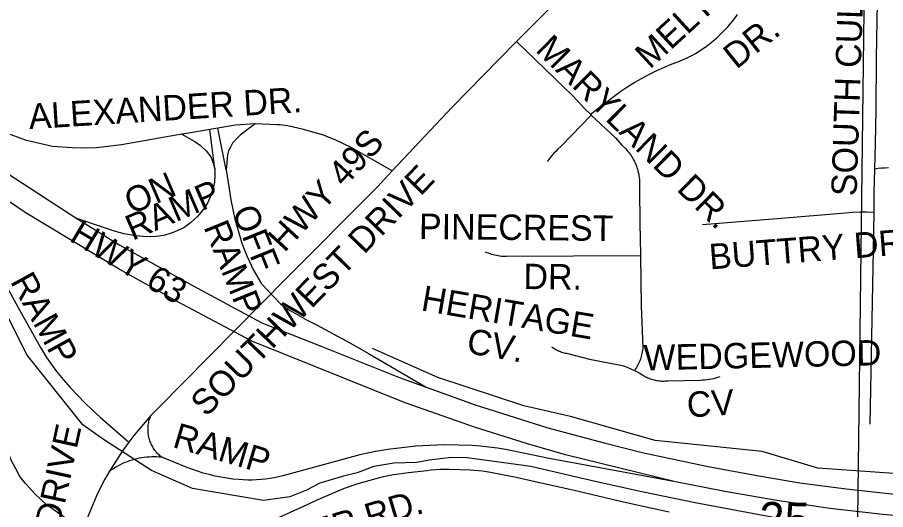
# Model space of a CAD drawing. Extents: x 1670563 to 1761545, y 515755 to 578944.
# Drawn here: x 1691143 to 1693706, y 539003 to 540456 of the extents above; entities that cross this region are included whole.
import ezdxf

# ---------------------------------------------------------------- set-up
doc = ezdxf.new("R2010")
doc.units = 0
for name, color, linetype in [('4_TwnRge', 7, 'Continuous'), ('62_text', 7, 'Continuous'), ('SHP_LINE', 7, 'Continuous'), ('STREETCL', 7, 'Continuous'), ('STRNAMES', 7, 'Continuous')]:
    doc.layers.add(name, color=color, linetype=linetype)

msp = doc.modelspace()

# ---------------------------------------------------------------- linework, layer by layer
at = {"layer": '4_TwnRge'}
msp.add_lwpolyline([(1693900.8, 565154.5), (1693867.8, 559919.3), (1693819.4, 554617.2), (1693735.2, 549363.2), (1693687.1, 544103.2), (1693620.9, 538819.1), (1693684.6, 533590.9), (1693722.5, 528338.7), (1693732, 528106.5), (1693805.9, 522944.4), (1693926.3, 517684.2)], dxfattribs=at)
at = {"layer": 'SHP_LINE'}
for points in [[(1693402, 538975), (1693144, 539023), (1692986, 539055), (1692848, 539086), (1692659, 539130), (1692471, 539156), (1692423, 539157), (1692358, 539149), (1692322, 539142), (1692254, 539140), (1692195, 539130), (1692146, 539112), (1692106, 539102), (1692036, 539081), (1691996, 539060), (1691947, 539041), (1691869, 539030), (1691660, 539065), (1691539, 539118), (1691397, 539210), (1691336, 539253), (1691172, 539459), (1691062, 539673)], [(1694077, 539095), (1693786, 539106), (1693506, 539125), (1693341, 539175), (1693026, 539207), (1692776, 539278), (1692638, 539309), (1692384, 539393), (1692191, 539479)]]:
    msp.add_lwpolyline(points, dxfattribs=at)
at = {"layer": 'STREETCL'}
for points in [[(1686352, 544277.5), (1686500.4, 544142.9), (1686643.4, 544011), (1686920.8, 543756), (1687195.3, 543505.5), (1687261.6, 543444.1), (1687480.5, 543242.8), (1687763.7, 542981.5), (1688044.1, 542723.1), (1688332.2, 542459.4), (1688615, 542198.1), (1688901.7, 541935.4), (1689188.3, 541672.2), (1689452.5, 541430), (1689667.4, 541231.7), (1689927.2, 540992.4), (1690019.9, 540907.5), (1690209.2, 540741.4), (1690477.2, 540495.7), (1690713.6, 540291), (1690921.7, 540133.1), (1691098.7, 540004.7), (1691318.5, 539862.7)], [(1692904.2, 540674.9), (1692616.6, 540384.4)], [(1693679.1, 540335.3), (1693679.6, 540392), (1693682.5, 540553.3), (1693683.9, 540651.4)], [(1692834.3, 540170.2), (1692904.8, 540223.3), (1692924.7, 540237.7), (1692945, 540251.5), (1692965.8, 540264.5), (1692987, 540276.7), (1693008.6, 540288.3), (1693030.6, 540299.1), (1693053, 540309.1), (1693075.7, 540318.4), (1693087.6, 540322.6), (1693099.3, 540327.2), (1693110.9, 540332.2), (1693122.3, 540337.6), (1693133.5, 540343.3), (1693144.5, 540349.4), (1693155.3, 540355.9), (1693165.8, 540362.8), (1693176.2, 540370), (1693186.3, 540377.5), (1693196.1, 540385.4), (1693207.6, 540395.5), (1693218.8, 540406.1), (1693229.5, 540417), (1693239.9, 540428.2), (1693249.9, 540439.9), (1693259.5, 540451.8), (1693268.7, 540464.1)], [(1691628.5, 540111.1), (1691450.5, 540080.1), (1691376.2, 540070.7), (1691336.3, 540069.8), (1691304.7, 540070.7), (1691246.1, 540074.4), (1691169.9, 540093), (1691105.7, 540116.2), (1691041.6, 540149.6), (1690971, 540198.9), (1690855.7, 540287.1), (1690697.8, 540413.5)], [(1692616.6, 540384.4), (1692566.2, 540333.5), (1692426.8, 540190.8), (1692249.6, 540002.5)], [(1692616.6, 540384.4), (1692757.9, 540248.4), (1692778.2, 540228.4), (1692797.9, 540207.7), (1692816.9, 540186.5), (1692834.3, 540170.2)], [(1690560.6, 540332.7), (1690789.8, 540085.9), (1690882, 539992.1), (1690902.1, 539971), (1690921.4, 539949.1), (1690940, 539926.5), (1690957.8, 539903.4), (1690974.7, 539879.6), (1691030.7, 539795.2), (1691083.7, 539708.9), (1691150.1, 539590.5), (1691211.2, 539481.6), (1691219.8, 539466.9), (1691228.8, 539452.4), (1691238.3, 539438.2), (1691248.2, 539424.3), (1691258.5, 539410.6), (1691278.2, 539386.6), (1691298.7, 539363.2), (1691319.9, 539340.4), (1691341.7, 539318.3), (1691364.2, 539296.8), (1691387.3, 539276), (1691471.3, 539201.6)], [(1693085.7, 539084.6), (1692761.1, 539164.6), (1692648.3, 539197.1), (1692491.9, 539246.3), (1692287.8, 539318.5), (1691834.5, 539500.2), (1691614, 539617.5), (1691443.2, 539712.3), (1691165.9, 539880.3), (1691006.9, 539986.9), (1690921.3, 540048.9), (1690851.5, 540099.1), (1690662.8, 540246.7), (1690560.6, 540332.7)], [(1693674.3, 540008.1), (1693676.1, 540083), (1693677.9, 540183.6), (1693679.1, 540335.3)], [(1691335, 538942.1), (1691227.4, 539018.5), (1691193.9, 539049.8), (1691179.2, 539066.3), (1691166.7, 539079.8), (1691149.8, 539100.4), (1691137.7, 539123.2), (1691123.2, 539151.1), (1691113.4, 539181.4), (1691105.7, 539211.7), (1691094, 539293.6), (1691082.3, 539412.9), (1691065.7, 539511.8), (1691042.7, 539591.8), (1691019, 539649.9), (1690982.5, 539719.5), (1690944.7, 539777.9), (1690828.4, 539932.8), (1690758.2, 540014.3), (1690579.2, 540190.5), (1690538, 540226.6)], [(1692837, 540167.6), (1692747.8, 540075.4), (1692737.6, 540065.8), (1692732.1, 540060.4), (1692726.7, 540054.8), (1692721.5, 540049), (1692716.5, 540043), (1692711.7, 540036.9), (1692707.1, 540030.7)], [(1692834.3, 540170.2), (1692837, 540167.6)], [(1692837, 540167.6), (1692908.6, 540100.5), (1692926.7, 540080.1), (1692938.6, 540067.7), (1692942, 540064), (1692945.3, 540060.2), (1692948.4, 540056.3), (1692951.4, 540052.3), (1692954.3, 540048.2), (1692957, 540044), (1692959.6, 540039.7), (1692962, 540035.3), (1692964.3, 540030.9), (1692966.4, 540026.3), (1692968.4, 540021.7), (1692970.2, 540017.1), (1692971.9, 540012.4), (1692973.4, 540007.6), (1692974.7, 540002.7), (1692975.9, 539997.9), (1692976.9, 539993), (1692977.8, 539988), (1692978.4, 539983.1), (1692978.9, 539978.1), (1692979.3, 539973.1), (1692979.4, 539968.1), (1692979.4, 539963.1), (1692979.2, 539958.1), (1692978.9, 539953.1), (1692980.6, 539845.1), (1692981.8, 539805.1), (1692982.4, 539752.4)], [(1691844.6, 540141.9), (1691787, 540137.6), (1691642, 540113.5), (1691628.5, 540111.1)], [(1691844.6, 540141.9), (1691800.7, 540108.1), (1691788.2, 540096), (1691778, 540084.2), (1691771.6, 540073), (1691766.5, 540061.9), (1691763.4, 540050.5), (1691762.1, 540039.7), (1691761, 540027), (1691758.9, 540006.4), (1691767.7, 539950.2), (1691773.3, 539917.3), (1691784.8, 539860.1), (1691806.7, 539786.9), (1691820.3, 539751.7), (1691839.5, 539709.8), (1691863, 539669.3), (1691920.2, 539609.8), (1691947.9, 539591), (1691996.5, 539563.2), (1692025.4, 539548.2), (1692125.8, 539494.3), (1692179.4, 539463.6), (1692221.2, 539439.1), (1692349.9, 539364.3)], [(1692249.6, 540002.5), (1692128.1, 540071.7), (1692081, 540094.5), (1692043.5, 540108.9), (1691983.1, 540125.6), (1691945, 540134.9), (1691940.7, 540135.4), (1691918, 540138.6), (1691908.7, 540138.6), (1691844.6, 540141.9)], [(1691628.5, 540111.1), (1691667, 540089.8), (1691683.5, 540077.7), (1691699.7, 540062.3), (1691713.6, 540043.9), (1691721.5, 540023.7), (1691725.3, 540008.9), (1691726, 539990.2), (1691724.5, 539969.3), (1691717.6, 539939.5), (1691705, 539909.1), (1691695.5, 539893.3), (1691675.6, 539868.7), (1691654.2, 539849.1), (1691633.7, 539835.2), (1691614.9, 539826.1), (1691599.7, 539820), (1691575.1, 539812.4), (1691552.7, 539809.1), (1691523.9, 539808.4), (1691492.4, 539811.2), (1691458, 539817.3), (1691432.3, 539823.7), (1691402.6, 539833.3), (1691318.5, 539862.7)], [(1691725.3, 540008.9), (1691710.5, 540124.9)], [(1691758.9, 540006.4), (1691734.6, 540128.9)], [(1693671.8, 539881.3), (1693672.6, 539938.4), (1693674.3, 540008.1)], [(1693714, 540011.4), (1693704.1, 540011.1), (1693694.1, 540010.4), (1693684.2, 540009.4), (1693674.3, 540008.1)], [(1692249.6, 540002.5), (1692205.7, 539955.8), (1691938.3, 539687.3), (1691557.4, 539301.9), (1691536.9, 539280.5)], [(1693165.5, 539844.3), (1693386.2, 539862.4), (1693587.6, 539879.4), (1693608.6, 539880.7), (1693629.7, 539881.5), (1693650.8, 539881.7), (1693671.8, 539881.3)], [(1693660.1, 539255.1), (1693670.3, 539769.1), (1693671.8, 539881.3)], [(1691318.5, 539862.7), (1691344, 539846.2), (1691445, 539783.4), (1691662, 539663.5), (1691864, 539554.3), (1692041.6, 539484.8), (1692267.4, 539394.1), (1692494.7, 539311.9), (1692708.9, 539244.7), (1692874.7, 539200.6), (1692987.4, 539171.8), (1693182.1, 539129.9), (1693331.8, 539102.5), (1693452.8, 539082.5), (1693589.9, 539064), (1693742.1, 539047.3)], [(1692982.4, 539752.4), (1692586.9, 539749.9), (1692581.9, 539749.9), (1692577, 539750.1), (1692572, 539750.5), (1692567.1, 539751.1), (1692562.2, 539751.8), (1692557.3, 539752.7), (1692552.5, 539753.7), (1692547.7, 539754.9), (1692542.9, 539756.3), (1692538.2, 539757.8), (1692533.5, 539759.5), (1692528.9, 539761.3), (1692524.4, 539763.3)], [(1692982.4, 539752.4), (1692984.1, 539603.3), (1692989.2, 539481.7), (1692988.8, 539477.3), (1692988.3, 539472.8), (1692987.6, 539468.4), (1692986.7, 539464), (1692985.7, 539459.6), (1692984.6, 539455.3), (1692983.3, 539451), (1692981.9, 539446.7), (1692980.3, 539442.6), (1692978.6, 539438.4), (1692976.7, 539434.3), (1692974.7, 539430.3), (1692972.6, 539426.4), (1692970.3, 539422.5), (1692968, 539418.7), (1692965.4, 539415)], [(1692720, 539483.5), (1692723.1, 539481.4), (1692726.2, 539479.4), (1692729.3, 539477.5), (1692732.6, 539475.6), (1692735.9, 539473.9), (1692739.2, 539472.3), (1692742.6, 539470.9), (1692746, 539469.5), (1692749.5, 539468.2), (1692753, 539467.1), (1692756.6, 539466.1), (1692760.2, 539465.1), (1692763.8, 539464.4), (1692767.4, 539463.7), (1692832.1, 539447), (1692929.2, 539428.2), (1692938.2, 539425), (1692947.2, 539421.5), (1692956, 539417.7), (1692964.8, 539413.6)], [(1692964.8, 539413.6), (1692972.5, 539409.6), (1692980.1, 539405.5), (1692987.6, 539401.1), (1692990.8, 539399.1), (1692994.1, 539397.2), (1692997.4, 539395.3), (1693000.8, 539393.6), (1693004.3, 539392.1), (1693007.8, 539390.6), (1693011.3, 539389.2), (1693014.9, 539388), (1693018.6, 539386.9), (1693022.3, 539385.9), (1693026, 539385.1), (1693029.7, 539384.3), (1693033.4, 539383.7), (1693037.2, 539383.2), (1693041, 539382.9), (1693044.8, 539382.6), (1693048.6, 539382.5), (1693052.4, 539382.6), (1693056.2, 539382.7), (1693060, 539383), (1693063.8, 539383.4), (1693159.8, 539385.5), (1693166.3, 539385.7), (1693172.7, 539386.2), (1693179.2, 539386.9), (1693185.7, 539387.9), (1693192.1, 539389), (1693198.4, 539390.4), (1693204.7, 539392), (1693211, 539393.9), (1693217.1, 539395.9)], [(1691536.9, 539280.5), (1691519.7, 539261.4), (1691503, 539241.9), (1691486.9, 539222), (1691471.3, 539201.6)], [(1691569.2, 539157.4), (1691566.4, 539159.7), (1691563.6, 539162), (1691560.9, 539164.4), (1691558.4, 539166.9), (1691555.9, 539169.5), (1691553.5, 539172.2), (1691551.2, 539175), (1691549, 539177.9), (1691546.9, 539180.8), (1691544.9, 539183.8), (1691543, 539186.9), (1691541.2, 539190), (1691539.5, 539193.2), (1691537.9, 539196.4), (1691536.5, 539199.7), (1691535.2, 539203.1), (1691533.9, 539206.5), (1691532.8, 539209.9), (1691531.9, 539213.4), (1691531, 539216.9), (1691530.3, 539220.4), (1691529.7, 539224), (1691529.2, 539227.6), (1691528.8, 539231.1), (1691528.6, 539234.7), (1691528.5, 539238.3), (1691528.5, 539241.9), (1691528.7, 539245.6), (1691528.9, 539249.1), (1691529.3, 539252.7), (1691529.8, 539256.3), (1691530.5, 539259.8), (1691531.2, 539263.4), (1691532.1, 539266.9), (1691533.1, 539270.3), (1691534.3, 539273.8), (1691535.5, 539277.1), (1691536.9, 539280.5)], [(1691471.3, 539201.6), (1691456.4, 539180.8), (1691441.9, 539159.7), (1691428.1, 539138.1), (1691414.9, 539116.2)], [(1693085.7, 539084.6), (1692708.2, 539154.8), (1692608.6, 539175.1), (1692584.2, 539180.1), (1692559.7, 539184.2), (1692535, 539187.6), (1692510.3, 539190.2), (1692485.4, 539192), (1692443.8, 539193.6), (1692402.1, 539193.8), (1692360.4, 539192.5), (1692318.8, 539189.8), (1692277.3, 539185.7), (1692236, 539180.1), (1692194.9, 539173.1), (1692154, 539164.7), (1691926.6, 539103.1), (1691913.9, 539099.9), (1691901.1, 539097.1), (1691888.2, 539094.8), (1691875.2, 539092.9), (1691862.1, 539091.5), (1691849, 539090.6), (1691835.9, 539090.1), (1691822.8, 539090), (1691809.7, 539090.5), (1691796.6, 539091.4), (1691778.8, 539093.2), (1691761.2, 539095.6), (1691743.6, 539098.6), (1691726.2, 539102.1), (1691708.8, 539106.3), (1691691.6, 539111), (1691674.6, 539116.2), (1691657.8, 539122.1), (1691641.1, 539128.5), (1691624.7, 539135.4), (1691569.2, 539157.4)], [(1691569.2, 539157.4), (1691561.8, 539158.1), (1691554.4, 539158.5), (1691546.9, 539158.7), (1691539.5, 539158.6), (1691532.1, 539158.3), (1691524.7, 539157.7), (1691517.3, 539156.9), (1691510, 539155.9), (1691502.7, 539154.5), (1691495.4, 539153), (1691488.2, 539151.2), (1691481, 539149.2), (1691474, 539146.9), (1691467, 539144.4), (1691460.1, 539141.6), (1691453.3, 539138.7), (1691446.6, 539135.5), (1691440, 539132), (1691433.5, 539128.4), (1691427.2, 539124.5), (1691420.9, 539120.5), (1691414.9, 539116.2)], [(1691414.9, 539116.2), (1691401.4, 539092.4), (1691388.6, 539068.1), (1691376.5, 539043.5), (1691356.6, 538996.9), (1691337.9, 538949.7)], [(1691866.7, 538958.5), (1692001.6, 539019.4), (1692026.2, 539031), (1692094.8, 539060.3), (1692108.8, 539066.1), (1692122.9, 539071.4), (1692137.2, 539076.4), (1692151.7, 539080.9), (1692166.3, 539085), (1692209.1, 539096.6), (1692223.5, 539100.3), (1692238.1, 539103.7), (1692252.8, 539106.6), (1692267.6, 539109), (1692282.5, 539111), (1692297.4, 539112.5), (1692351.1, 539118.9), (1692364.6, 539120.3), (1692378.2, 539121.3), (1692391.7, 539122), (1692405.3, 539122.2), (1692418.9, 539122.1), (1692479.6, 539120), (1692491.7, 539119.4), (1692503.8, 539118.4), (1692515.9, 539117), (1692527.9, 539115.3), (1692539.8, 539113.1), (1692615, 539098.9), (1692679.9, 539084.4), (1692782.6, 539061.2), (1692878, 539038.6), (1692919.7, 539028.7), (1693002.5, 539010.5), (1693067, 538996.9)], [(1696670.7, 538973.8), (1696333.5, 538971), (1696148, 538969.5), (1695470.7, 538964.4), (1695374.3, 538964.4), (1694484.4, 538957.6), (1694324.4, 538956.2), (1694203.3, 538957), (1694082.3, 538961.6), (1693950.7, 538967.5), (1693790.3, 538979.4), (1693688.8, 538989.6), (1693541.6, 539006.6), (1693384.7, 539029.7), (1693231.4, 539056.3), (1693085.7, 539084.6)]]:
    msp.add_lwpolyline(points, dxfattribs=at)

# ---------------------------------------------------------------- texts
at = {"layer": '62_text'}
msp.add_text('25', height=100, rotation=358.9319, dxfattribs=at).set_placement((1693332.1, 538926))
at = {"layer": 'STRNAMES'}
for s, rotation, p in [('SOUTH CULBERHOUSE', 88.1068, (1693620.2, 539927.2)), ('MELTON', 42.61, (1693009.7, 540301.2)), ('DR.', 38.4878, (1693265.2, 540300.9)), ('MARYLAND DR.', 315.42, (1692669.5, 540357.6)), ('ALEXANDER DR.', 3.5821, (1691178.1, 540125.8)), ('  HWY 49S', 47.3495, (1691893.4, 539718.5)), ('SOUTHWEST DRIVE  ', 45.915, (1691700.8, 539273.9)), ('ON', 23.2826, (1691479.7, 539873.4)), ('RAMP', 23.2826, (1691482.6, 539796)), ('OFF', 291.9634, (1691775.2, 539883.8)), ('HWY 63', 329.0862, (1691293, 539798.1)), ('RAMP', 291.9634, (1691691.6, 539837.5)), ('PINECREST', 359.4129, (1692328.1, 539801.8)), ('BUTTRY DR.', 4.4213, (1693187.7, 539711.9)), ('DR.', 359.4129, (1692636.5, 539654)), ('RAMP', 298.7629, (1691120.4, 539676.7)), ('HERITAGE', 350.3011, (1692331.8, 539591.3)), (' CV.', 350.3011, (1692438.7, 539470)), ('WEDGEWOOD', 1.2555, (1692992.1, 539413.9)), ('CV', 3.782, (1693121.6, 539274.8)), ('SOUTHWEST DRIVE', 77.7717, (1691125.5, 538292.2)), ('RAMP', 343.5519, (1691597.7, 539188.4)), ('PARKER RD.', 16.6352, (1691759.5, 538818.9))]:
    msp.add_text(s, height=75, rotation=rotation, dxfattribs=at).set_placement(p)

doc.saveas('drawing.dxf')
